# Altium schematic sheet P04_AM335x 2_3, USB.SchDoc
size 513 x 386 mm
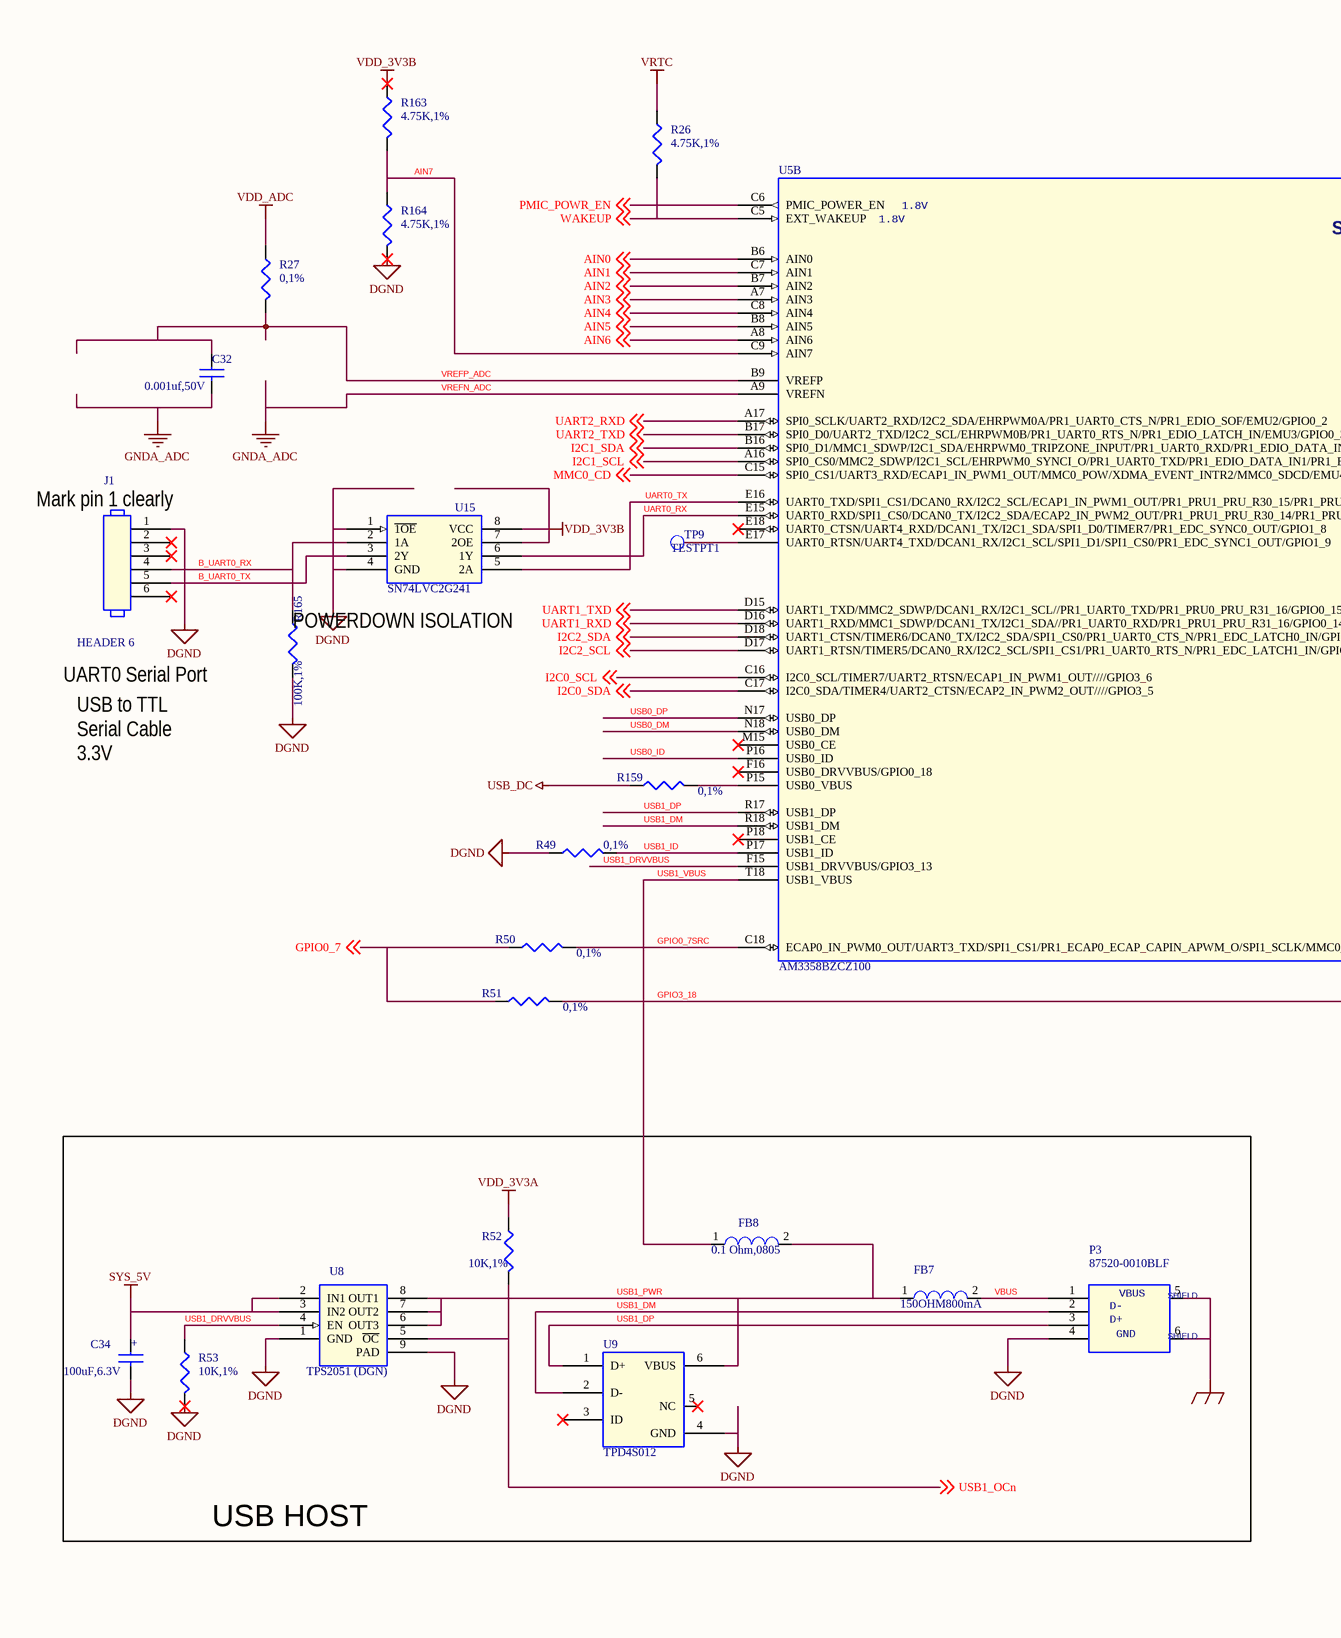
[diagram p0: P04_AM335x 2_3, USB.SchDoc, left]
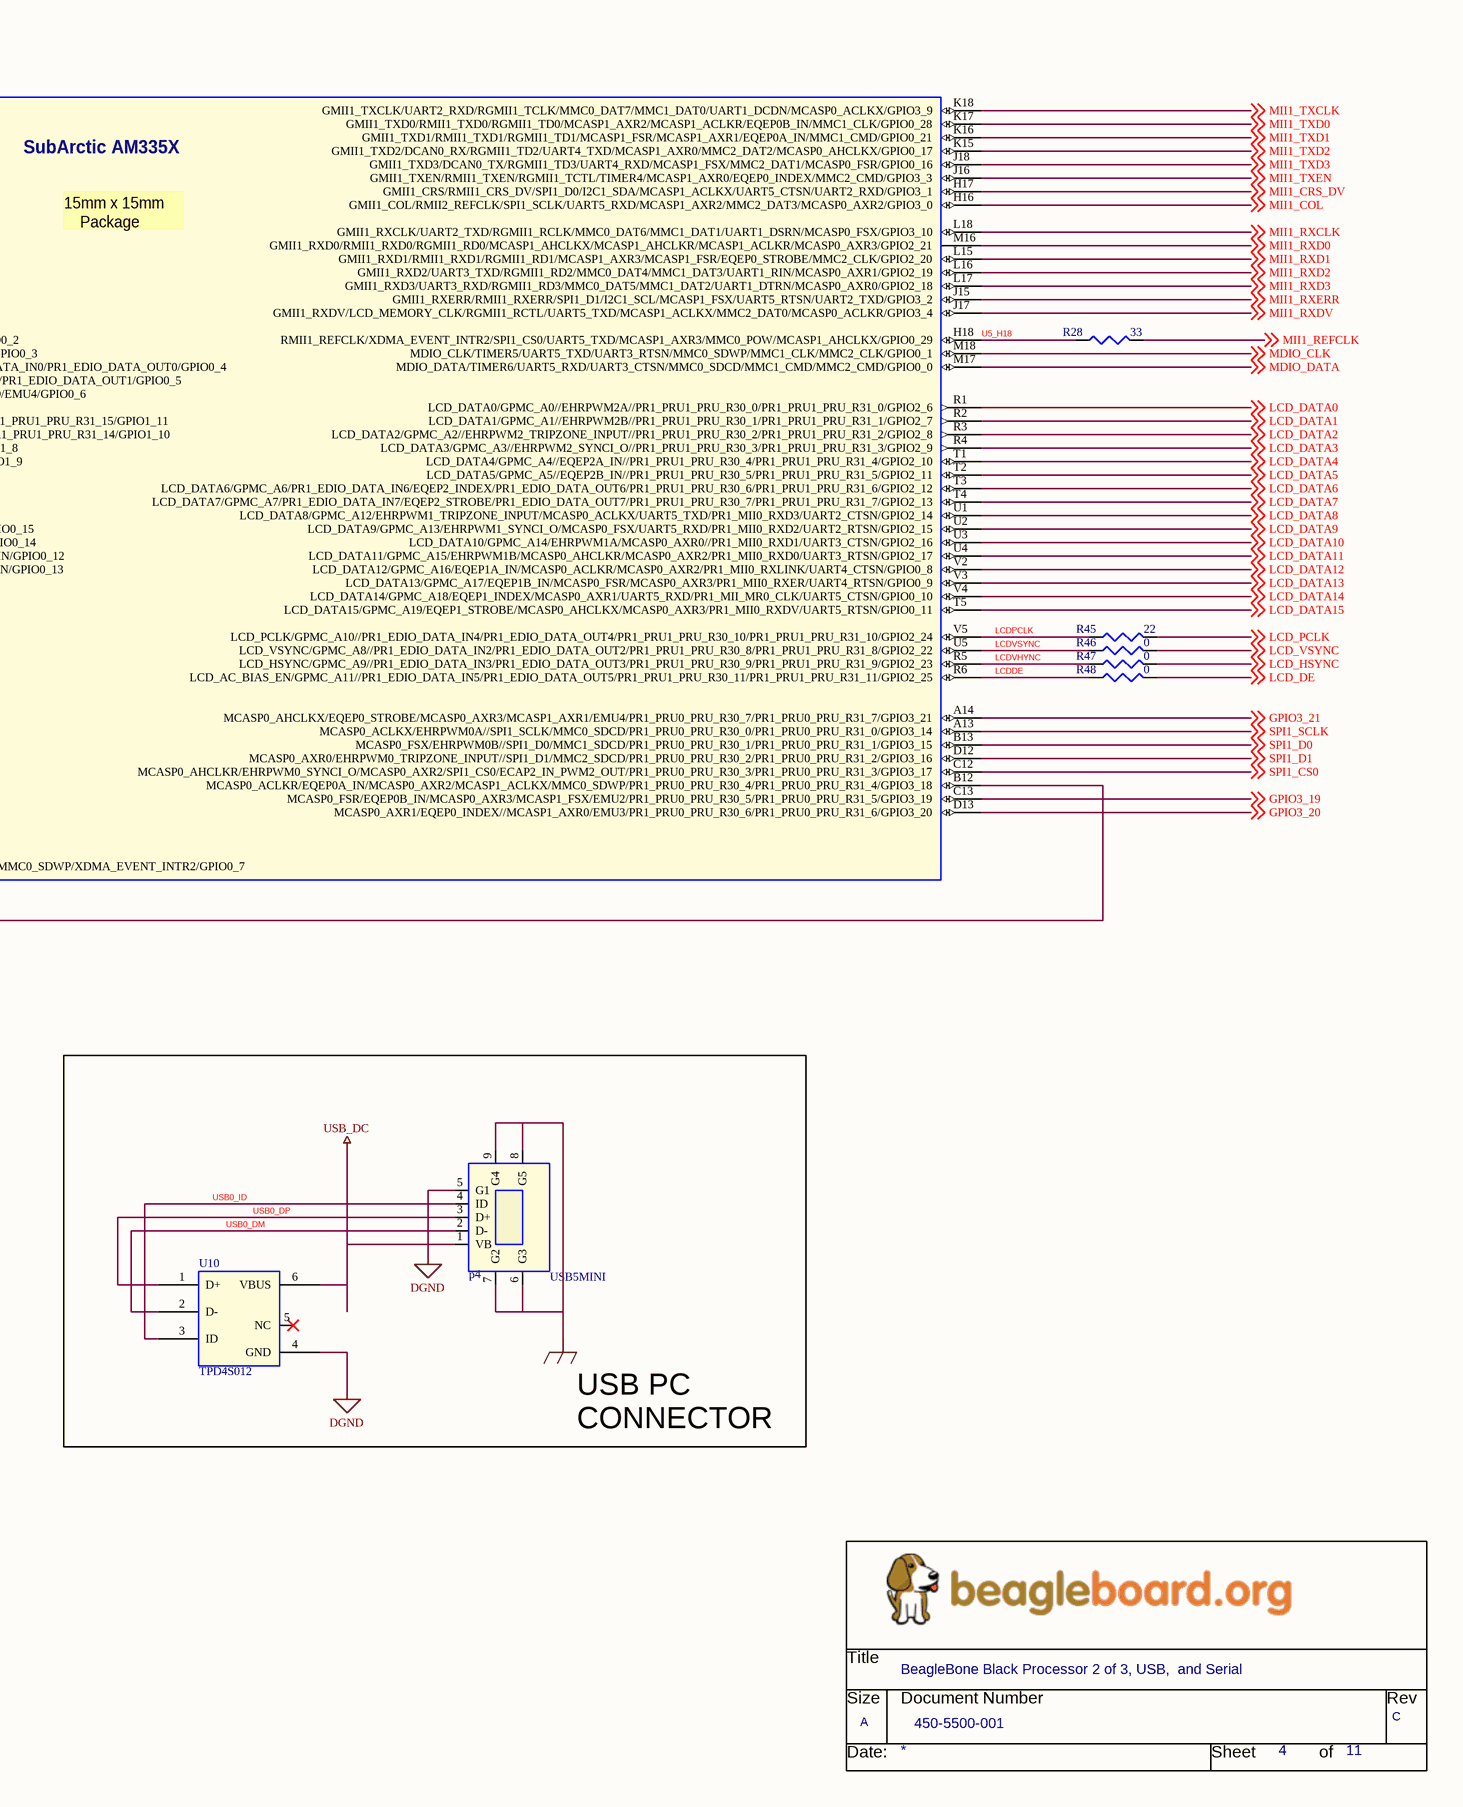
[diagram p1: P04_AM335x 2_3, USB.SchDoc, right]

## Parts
*  Page Count: 11  Page Number: 4  Page Size: A  Title: BeagleBone Black Processor 2 of 3, USB,  and Serial  RevCode: C  Doc: 450-5500-001  (hidden comment: BeagleBoard_org)  (graphical)
C32  0.001uf,50V  [402]
C34  100uF,6.3V  [r402-25rd]
FB7  150OHM800mA  [L0805]
FB8  0.1 Ohm,0805  [L0805]
J1  HEADER 6  [SIP6]
P3  87520-0010BLF  [MOL-54819-0578]
p4  USB5MINI  [usb-mini-smt-num]
R26  4.75K,1%  [402]
R27  0,1%  [402]
R28  33  [r402-25rd]
R45  22  [r402-25rd]
R46  0  [r402-25rd]
R47  0  [r402-25rd]
R48  0  [r402-25rd]
R49  0,1%  [402]
R50  0,1%  [402]
R51  0,1%  [402]
R52  10K,1%  [402]
R53  10K,1%  [402]
R159  0,1%  [402]
R163  4.75K,1%  [402]
R164  4.75K,1%  [402]
R165  100K,1%  [402]
TP9  TESTPT1  [tp1-8040]
U5  AM3358BZCZ100  [am33xx_15x15]  (part B of 3)
U8  TPS2051 (DGN)  [DGN-16X60]
U9  TPD4S012  [U_6_DRY]
U10  TPD4S012  [U_6_DRY]
U15  SN74LVC2G241  [U_8_DCU]

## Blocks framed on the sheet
USB HOST: C34 FB7 FB8 P3 R52 R53 U8 U9

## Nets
DGND: C34.2 J1.1 P3.4(P4) p4.5(G1) R49.1 R53.2 R164.2 R165.2 U8.1(GND) U8.9(PAD) U9.4(GND) U10.4(GND) U15.1(~{1OE}) U15.4(GND)
GND_EARTH: P3.5(SHELD1) P3.6(PAD4) p4.6(G3) p4.7(G2) p4.8(G5) p4.9(G4)
SYS_5V: C34.1 U8.2(IN1) U8.3(IN2)
USB_DC: p4.1(VB) R159.1 U10.6(VBUS)
VDD_3V3A: R52.1
VDD_3V3B: R163.1 U15.7(2OE) U15.8(VCC)
VDD_ADC: R27.1
VREFN_ADC: C32.2 U5.A9(VREFN)  [also labelled GNDA_ADC]
VRTC: R26.1
AIN0: U5.B6(AIN0) ; off-sheet AIN0
AIN1: U5.C7(AIN1) ; off-sheet AIN1
AIN2: U5.B7(AIN2) ; off-sheet AIN2
AIN3: U5.A7(AIN3) ; off-sheet AIN3
AIN4: U5.C8(AIN4) ; off-sheet AIN4
AIN5: U5.B8(AIN5) ; off-sheet AIN5
AIN6: U5.A8(AIN6) ; off-sheet AIN6
AIN7: R163.2 R164.1 U5.C9(AIN7)
B_UART0_RX: J1.4 R165.1 U15.2(1A)
B_UART0_TX: J1.5 U15.3(2Y)
GPIO0_7: R50.1 R51.1 ; off-sheet GPIO0_7
GPIO0_7SRC: R50.2 U5.C18(ECAP0_IN_PWM0_OUT/UART3_TXD/SPI1_CS1/PR1_ECAP0_ECAP_CAPIN_APWM_O/SPI1_SCLK/MMC0_SDWP/XDMA_EVENT_INTR2/GPIO0_7)
GPIO3_18: R51.2 U5.B12(MCASP0_ACLKR/EQEP0A_IN/MCASP0_AXR2/MCASP1_ACLKX/MMC0_SDWP/PR1_PRU0_PRU_R30_4/PR1_PRU0_PRU_R31_4/GPIO3_18)
GPIO3_19: U5.C13(MCASP0_FSR/EQEP0B_IN/MCASP0_AXR3/MCASP1_FSX/EMU2/PR1_PRU0_PRU_R30_5/PR1_PRU0_PRU_R31_5/GPIO3_19) ; off-sheet GPIO3_19
GPIO3_20: U5.D13(MCASP0_AXR1/EQEP0_INDEX//MCASP1_AXR0/EMU3/PR1_PRU0_PRU_R30_6/PR1_PRU0_PRU_R31_6/GPIO3_20) ; off-sheet GPIO3_20
GPIO3_21: U5.A14(MCASP0_AHCLKX/EQEP0_STROBE/MCASP0_AXR3/MCASP1_AXR1/EMU4/PR1_PRU0_PRU_R30_7/PR1_PRU0_PRU_R31_7/GPIO3_21) ; off-sheet GPIO3_21
I2C0_SCL: U5.C16(I2C0_SCL/TIMER7/UART2_RTSN/ECAP1_IN_PWM1_OUT////GPIO3_6) ; off-sheet I2C0_SCL
I2C0_SDA: U5.C17(I2C0_SDA/TIMER4/UART2_CTSN/ECAP2_IN_PWM2_OUT////GPIO3_5) ; off-sheet I2C0_SDA
I2C1_SCL: U5.A16(SPI0_CS0/MMC2_SDWP/I2C1_SCL/EHRPWM0_SYNCI_O/PR1_UART0_TXD/PR1_EDIO_DATA_IN1/PR1_EDIO_DATA_OUT1/GPIO0_5) ; off-sheet I2C1_SCL
I2C1_SDA: U5.B16(SPI0_D1/MMC1_SDWP/I2C1_SDA/EHRPWM0_TRIPZONE_INPUT/PR1_UART0_RXD/PR1_EDIO_DATA_IN0/PR1_EDIO_DATA_OUT0/GPIO0_4) ; off-sheet I2C1_SDA
I2C2_SCL: U5.D17(UART1_RTSN/TIMER5/DCAN0_RX/I2C2_SCL/SPI1_CS1/PR1_UART0_RTS_N/PR1_EDC_LATCH1_IN/GPIO0_13) ; off-sheet I2C2_SCL
I2C2_SDA: U5.D18(UART1_CTSN/TIMER6/DCAN0_TX/I2C2_SDA/SPI1_CS0/PR1_UART0_CTS_N/PR1_EDC_LATCH0_IN/GPIO0_12) ; off-sheet I2C2_SDA
LCD_DATA0: U5.R1(LCD_DATA0/GPMC_A0//EHRPWM2A//PR1_PRU1_PRU_R30_0/PR1_PRU1_PRU_R31_0/GPIO2_6) ; off-sheet LCD_DATA0
LCD_DATA1: U5.R2(LCD_DATA1/GPMC_A1//EHRPWM2B//PR1_PRU1_PRU_R30_1/PR1_PRU1_PRU_R31_1/GPIO2_7) ; off-sheet LCD_DATA1
LCD_DATA2: U5.R3(LCD_DATA2/GPMC_A2//EHRPWM2_TRIPZONE_INPUT//PR1_PRU1_PRU_R30_2/PR1_PRU1_PRU_R31_2/GPIO2_8) ; off-sheet LCD_DATA2
LCD_DATA3: U5.R4(LCD_DATA3/GPMC_A3//EHRPWM2_SYNCI_O//PR1_PRU1_PRU_R30_3/PR1_PRU1_PRU_R31_3/GPIO2_9) ; off-sheet LCD_DATA3
LCD_DATA4: U5.T1(LCD_DATA4/GPMC_A4//EQEP2A_IN//PR1_PRU1_PRU_R30_4/PR1_PRU1_PRU_R31_4/GPIO2_10) ; off-sheet LCD_DATA4
LCD_DATA5: U5.T2(LCD_DATA5/GPMC_A5//EQEP2B_IN//PR1_PRU1_PRU_R30_5/PR1_PRU1_PRU_R31_5/GPIO2_11) ; off-sheet LCD_DATA5
LCD_DATA6: U5.T3(LCD_DATA6/GPMC_A6/PR1_EDIO_DATA_IN6/EQEP2_INDEX/PR1_EDIO_DATA_OUT6/PR1_PRU1_PRU_R30_6/PR1_PRU1_PRU_R31_6/GPIO2_12) ; off-sheet LCD_DATA6
LCD_DATA7: U5.T4(LCD_DATA7/GPMC_A7/PR1_EDIO_DATA_IN7/EQEP2_STROBE/PR1_EDIO_DATA_OUT7/PR1_PRU1_PRU_R30_7/PR1_PRU1_PRU_R31_7/GPIO2_13) ; off-sheet LCD_DATA7
LCD_DATA8: U5.U1(LCD_DATA8/GPMC_A12/EHRPWM1_TRIPZONE_INPUT/MCASP0_ACLKX/UART5_TXD/PR1_MII0_RXD3/UART2_CTSN/GPIO2_14) ; off-sheet LCD_DATA8
LCD_DATA9: U5.U2(LCD_DATA9/GPMC_A13/EHRPWM1_SYNCI_O/MCASP0_FSX/UART5_RXD/PR1_MII0_RXD2/UART2_RTSN/GPIO2_15) ; off-sheet LCD_DATA9
LCD_DATA10: U5.U3(LCD_DATA10/GPMC_A14/EHRPWM1A/MCASP0_AXR0//PR1_MII0_RXD1/UART3_CTSN/GPIO2_16) ; off-sheet LCD_DATA10
LCD_DATA11: U5.U4(LCD_DATA11/GPMC_A15/EHRPWM1B/MCASP0_AHCLKR/MCASP0_AXR2/PR1_MII0_RXD0/UART3_RTSN/GPIO2_17) ; off-sheet LCD_DATA11
LCD_DATA12: U5.V2(LCD_DATA12/GPMC_A16/EQEP1A_IN/MCASP0_ACLKR/MCASP0_AXR2/PR1_MII0_RXLINK/UART4_CTSN/GPIO0_8) ; off-sheet LCD_DATA12
LCD_DATA13: U5.V3(LCD_DATA13/GPMC_A17/EQEP1B_IN/MCASP0_FSR/MCASP0_AXR3/PR1_MII0_RXER/UART4_RTSN/GPIO0_9) ; off-sheet LCD_DATA13
LCD_DATA14: U5.V4(LCD_DATA14/GPMC_A18/EQEP1_INDEX/MCASP0_AXR1/UART5_RXD/PR1_MII_MR0_CLK/UART5_CTSN/GPIO0_10) ; off-sheet LCD_DATA14
LCD_DATA15: U5.T5(LCD_DATA15/GPMC_A19/EQEP1_STROBE/MCASP0_AHCLKX/MCASP0_AXR3/PR1_MII0_RXDV/UART5_RTSN/GPIO0_11) ; off-sheet LCD_DATA15
LCD_DE: R48.2 ; off-sheet LCD_DE
LCD_HSYNC: R47.2 ; off-sheet LCD_HSYNC
LCD_PCLK: R45.2 ; off-sheet LCD_PCLK
LCD_VSYNC: R46.2 ; off-sheet LCD_VSYNC
LCDDE: R48.1 U5.R6(LCD_AC_BIAS_EN/GPMC_A11//PR1_EDIO_DATA_IN5/PR1_EDIO_DATA_OUT5/PR1_PRU1_PRU_R30_11/PR1_PRU1_PRU_R31_11/GPIO2_25)
LCDPCLK: R45.1 U5.V5(LCD_PCLK/GPMC_A10//PR1_EDIO_DATA_IN4/PR1_EDIO_DATA_OUT4/PR1_PRU1_PRU_R30_10/PR1_PRU1_PRU_R31_10/GPIO2_24)
LCDVHYNC: R47.1 U5.R5(LCD_HSYNC/GPMC_A9//PR1_EDIO_DATA_IN3/PR1_EDIO_DATA_OUT3/PR1_PRU1_PRU_R30_9/PR1_PRU1_PRU_R31_9/GPIO2_23)
LCDVSYNC: R46.1 U5.U5(LCD_VSYNC/GPMC_A8//PR1_EDIO_DATA_IN2/PR1_EDIO_DATA_OUT2/PR1_PRU1_PRU_R30_8/PR1_PRU1_PRU_R31_8/GPIO2_22)
MDIO_CLK: U5.M18(MDIO_CLK/TIMER5/UART5_TXD/UART3_RTSN/MMC0_SDWP/MMC1_CLK/MMC2_CLK/GPIO0_1) ; off-sheet MDIO_CLK
MDIO_DATA: U5.M17(MDIO_DATA/TIMER6/UART5_RXD/UART3_CTSN/MMC0_SDCD/MMC1_CMD/MMC2_CMD/GPIO0_0) ; off-sheet MDIO_DATA
MII1_COL: U5.H16(GMII1_COL/RMII2_REFCLK/SPI1_SCLK/UART5_RXD/MCASP1_AXR2/MMC2_DAT3/MCASP0_AXR2/GPIO3_0) ; off-sheet MII1_COL
MII1_CRS_DV: U5.H17(GMII1_CRS/RMII1_CRS_DV/SPI1_D0/I2C1_SDA/MCASP1_ACLKX/UART5_CTSN/UART2_RXD/GPIO3_1) ; off-sheet MII1_CRS_DV
MII1_REFCLK: R28.2 ; off-sheet MII1_REFCLK
MII1_RXCLK: U5.L18(GMII1_RXCLK/UART2_TXD/RGMII1_RCLK/MMC0_DAT6/MMC1_DAT1/UART1_DSRN/MCASP0_FSX/GPIO3_10) ; off-sheet MII1_RXCLK
MII1_RXD0: U5.M16(GMII1_RXD0/RMII1_RXD0/RGMII1_RD0/MCASP1_AHCLKX/MCASP1_AHCLKR/MCASP1_ACLKR/MCASP0_AXR3/GPIO2_21) ; off-sheet MII1_RXD0
MII1_RXD1: U5.L15(GMII1_RXD1/RMII1_RXD1/RGMII1_RD1/MCASP1_AXR3/MCASP1_FSR/EQEP0_STROBE/MMC2_CLK/GPIO2_20) ; off-sheet MII1_RXD1
MII1_RXD2: U5.L16(GMII1_RXD2/UART3_TXD/RGMII1_RD2/MMC0_DAT4/MMC1_DAT3/UART1_RIN/MCASP0_AXR1/GPIO2_19) ; off-sheet MII1_RXD2
MII1_RXD3: U5.L17(GMII1_RXD3/UART3_RXD/RGMII1_RD3/MMC0_DAT5/MMC1_DAT2/UART1_DTRN/MCASP0_AXR0/GPIO2_18) ; off-sheet MII1_RXD3
MII1_RXDV: U5.J17(GMII1_RXDV/LCD_MEMORY_CLK/RGMII1_RCTL/UART5_TXD/MCASP1_ACLKX/MMC2_DAT0/MCASP0_ACLKR/GPIO3_4) ; off-sheet MII1_RXDV
MII1_RXERR: U5.J15(GMII1_RXERR/RMII1_RXERR/SPI1_D1/I2C1_SCL/MCASP1_FSX/UART5_RTSN/UART2_TXD/GPIO3_2) ; off-sheet MII1_RXERR
MII1_TXCLK: U5.K18(GMII1_TXCLK/UART2_RXD/RGMII1_TCLK/MMC0_DAT7/MMC1_DAT0/UART1_DCDN/MCASP0_ACLKX/GPIO3_9) ; off-sheet MII1_TXCLK
MII1_TXD0: U5.K17(GMII1_TXD0/RMII1_TXD0/RGMII1_TD0/MCASP1_AXR2/MCASP1_ACLKR/EQEP0B_IN/MMC1_CLK/GPIO0_28) ; off-sheet MII1_TXD0
MII1_TXD1: U5.K16(GMII1_TXD1/RMII1_TXD1/RGMII1_TD1/MCASP1_FSR/MCASP1_AXR1/EQEP0A_IN/MMC1_CMD/GPIO0_21) ; off-sheet MII1_TXD1
MII1_TXD2: U5.K15(GMII1_TXD2/DCAN0_RX/RGMII1_TD2/UART4_TXD/MCASP1_AXR0/MMC2_DAT2/MCASP0_AHCLKX/GPIO0_17) ; off-sheet MII1_TXD2
MII1_TXD3: U5.J18(GMII1_TXD3/DCAN0_TX/RGMII1_TD3/UART4_RXD/MCASP1_FSX/MMC2_DAT1/MCASP0_FSR/GPIO0_16) ; off-sheet MII1_TXD3
MII1_TXEN: U5.J16(GMII1_TXEN/RMII1_TXEN/RGMII1_TCTL/TIMER4/MCASP1_AXR0/EQEP0_INDEX/MMC2_CMD/GPIO3_3) ; off-sheet MII1_TXEN
MMC0_CD: U5.C15(SPI0_CS1/UART3_RXD/ECAP1_IN_PWM1_OUT/MMC0_POW/XDMA_EVENT_INTR2/MMC0_SDCD/EMU4/GPIO0_6) ; off-sheet MMC0_CD
PMIC_POWR_EN: U5.C6(PMIC_POWER_EN) ; off-sheet PMIC_POWR_EN
SPI1_CS0: U5.C12(MCASP0_AHCLKR/EHRPWM0_SYNCI_O/MCASP0_AXR2/SPI1_CS0/ECAP2_IN_PWM2_OUT/PR1_PRU0_PRU_R30_3/PR1_PRU0_PRU_R31_3/GPIO3_17) ; off-sheet SPI1_CS0
SPI1_D0: U5.B13(MCASP0_FSX/EHRPWM0B//SPI1_D0/MMC1_SDCD/PR1_PRU0_PRU_R30_1/PR1_PRU0_PRU_R31_1/GPIO3_15) ; off-sheet SPI1_D0
SPI1_D1: U5.D12(MCASP0_AXR0/EHRPWM0_TRIPZONE_INPUT//SPI1_D1/MMC2_SDCD/PR1_PRU0_PRU_R30_2/PR1_PRU0_PRU_R31_2/GPIO3_16) ; off-sheet SPI1_D1
SPI1_SCLK: U5.A13(MCASP0_ACLKX/EHRPWM0A//SPI1_SCLK/MMC0_SDCD/PR1_PRU0_PRU_R30_0/PR1_PRU0_PRU_R31_0/GPIO3_14) ; off-sheet SPI1_SCLK
U5_H18: R28.1 U5.H18(RMII1_REFCLK/XDMA_EVENT_INTR2/SPI1_CS0/UART5_TXD/MCASP1_AXR3/MMC0_POW/MCASP1_AHCLKX/GPIO0_29)
UART0_RX: U5.E15(UART0_RXD/SPI1_CS0/DCAN0_TX/I2C2_SDA/ECAP2_IN_PWM2_OUT/PR1_PRU1_PRU_R30_14/PR1_PRU1_PRU_R31_14/GPIO1_10) U15.6(1Y)
UART0_TX: U5.E16(UART0_TXD/SPI1_CS1/DCAN0_RX/I2C2_SCL/ECAP1_IN_PWM1_OUT/PR1_PRU1_PRU_R30_15/PR1_PRU1_PRU_R31_15/GPIO1_11) U15.5(2A)
UART1_RXD: U5.D16(UART1_RXD/MMC1_SDWP/DCAN1_TX/I2C1_SDA//PR1_UART0_RXD/PR1_PRU1_PRU_R31_16/GPIO0_14) ; off-sheet UART1_RXD
UART1_TXD: U5.D15(UART1_TXD/MMC2_SDWP/DCAN1_RX/I2C1_SCL//PR1_UART0_TXD/PR1_PRU0_PRU_R31_16/GPIO0_15) ; off-sheet UART1_TXD
UART2_RXD: U5.A17(SPI0_SCLK/UART2_RXD/I2C2_SDA/EHRPWM0A/PR1_UART0_CTS_N/PR1_EDIO_SOF/EMU2/GPIO0_2) ; off-sheet UART2_RXD
UART2_TXD: U5.B17(SPI0_D0/UART2_TXD/I2C2_SCL/EHRPWM0B/PR1_UART0_RTS_N/PR1_EDIO_LATCH_IN/EMU3/GPIO0_3) ; off-sheet UART2_TXD
USB0_DM: p4.2(D-) U5.N18(USB0_DM) U10.2(D-)
USB0_DP: p4.3(D+) U5.N17(USB0_DP) U10.1(D+)
USB0_ID: p4.4(ID) U5.P16(USB0_ID) U10.3(ID)
USB1_DM: P3.2(P2) U5.R18(USB1_DM) U9.2(D-)
USB1_DP: P3.3(P3) U5.R17(USB1_DP) U9.1(D+)
USB1_DRVVBUS: R53.1 U5.F15(USB1_DRVVBUS/GPIO3_13) U8.4(EN)
USB1_ID: R49.2 U5.P17(USB1_ID)
USB1_OCn: R52.2 U8.5(~{OC}) ; off-sheet USB1_OCn
USB1_PWR: FB7.1 FB8.2 U8.6(OUT3) U8.7(OUT2) U8.8(OUT1) U9.6(VBUS)
USB1_VBUS: FB8.1 U5.T18(USB1_VBUS)
VBUS: FB7.2 P3.1(P1)
VREFP_ADC: C32.1 R27.2 U5.B9(VREFP)
WAKEUP: R26.2 U5.C5(EXT_WAKEUP) ; off-sheet WAKEUP
NetR159_2: R159.2 U5.P15(USB0_VBUS)
NetTP9_1: TP9.1(TP) U5.E17(UART0_RTSN/UART4_TXD/DCAN1_RX/I2C1_SCL/SPI1_D1/SPI1_CS0/PR1_EDC_SYNC1_OUT/GPIO1_9)

Not connected (* = marked no-connect by the designer): J1 2* 3* 6*; U5 E18(UART0_CTSN/UART4_RXD/DCAN1_TX/I2C1_SDA/SPI1_D0/TIMER7/PR1_EDC_SYNC0_OUT/GPIO1_8)* F16(USB0_DRVVBUS/GPIO0_18)* M15(USB0_CE)* P18(USB1_CE)*; U9 3(ID)* 5(NC)*; U10 5(NC)*

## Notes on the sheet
- (near J1) Mark pin 1 clearly
- (near R165) POWERDOWN ISOLATION
- UART0 Serial Port
- USB to TTL
  Serial Cable
  3.3V
- USB PC
  CONNECTOR

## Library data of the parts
C32 = CAP_0.001_X7R_50V_5%_0402: Part Number: CAP_0.001uf_X7R_50V_0402; Desc: Capacitor 0.001uF 50V 5% 0402
C34 = CAP_100UF_TANT_6.3V_3528-21: Desc: CAP CER 100UF 10V Y5V 0805; PCB Footprint: RD205SMD_250D
FB7 FB8 = FER_180_200_0: Ferrite Bead 150 Ohm 800mA; Part Number: FER_180_200_0805; TIIntPartnumber: 1L0010; MfrNum: LI0805H151R-10; Mfr: Steward; PCB Footprint: 805; Vendor: Digikey
P3 = CONN_54819-0578_2: TN: 224-0234-000; CLASS: IO; PCB Footprint: USB_A_SH
p4 = MINI-USB-AB-SOCKET: Manufacturer: KYCON; Order#: KMAB-SMT-5S-S-30TR; ATLStockNo1: 4500.0223; Order# 2: C-440247; PCB Footprint: USB5MINI_4SHIELDED_SMD-5
R26 R50 R51 R159 R163 R164 = RES_4.75K_1/16W_1%_0402: RES 4.75K OHM 1/16W 1% 0402 SMD
R27 = RES_0_1/16W_1%_0402_Dup1: Resistor Zero ohm Jumper 0402
R28 R45-R48 = RES_33_0402: PCB Footprint: 0402
R49 R165 = RES_100K_1/16W_1%_0402: Resistor 100Kohm 1/16W 1% 0402
R52 R53 = RES_10K_1/16W_1%_0402_Dup1: Resistor 10Kohm 1/16W 1% 0402
TP9 = TESTPT1: PCB Footprint: TP60C33D
U5 = IC_AM335X_ZCZ: SubArctic Cortex A8 Processor 15x15; Part Number: IC_AM335x_ZCE; TIIntPartnumber: 1A0242; MfrNum: AM335x 15x15 FBGA ZCE; Mfr: TI; PartName: AM335X_15x15; PCB Footprint: FBGAZCZ15x15_tbd; Vendor: Arrow; Cost10K: 10.00
U8 = TPS2061_1
U9 U10 = PROT_TPD4S012: ESD 4channel USB Interface; TIIntPartnumber: 1A0233; MfrNum: TPD4S012DRY; Mfr: TI; PCB Footprint: smd UFDFN-6pin; Cost10K: 0.23; Cost100: 0.76; Vendor: Digikey
U15 = IC_SN74LVC2G241_1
